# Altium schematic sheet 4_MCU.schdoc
size 309 x 223 mm; Symbol: Artery_A4; Device: Artery_A4; Company: Artery Technology; Drawed: SD; Version: 1.0; Page Size: A4; @Project Name: AT-START-F405; @Page Count: 4; @Update Date: 2023-08-23; @Create Date: 2023-05-06; @Schematic Name: AT-START-F405; @Page No: 2; @Page Name: MCU
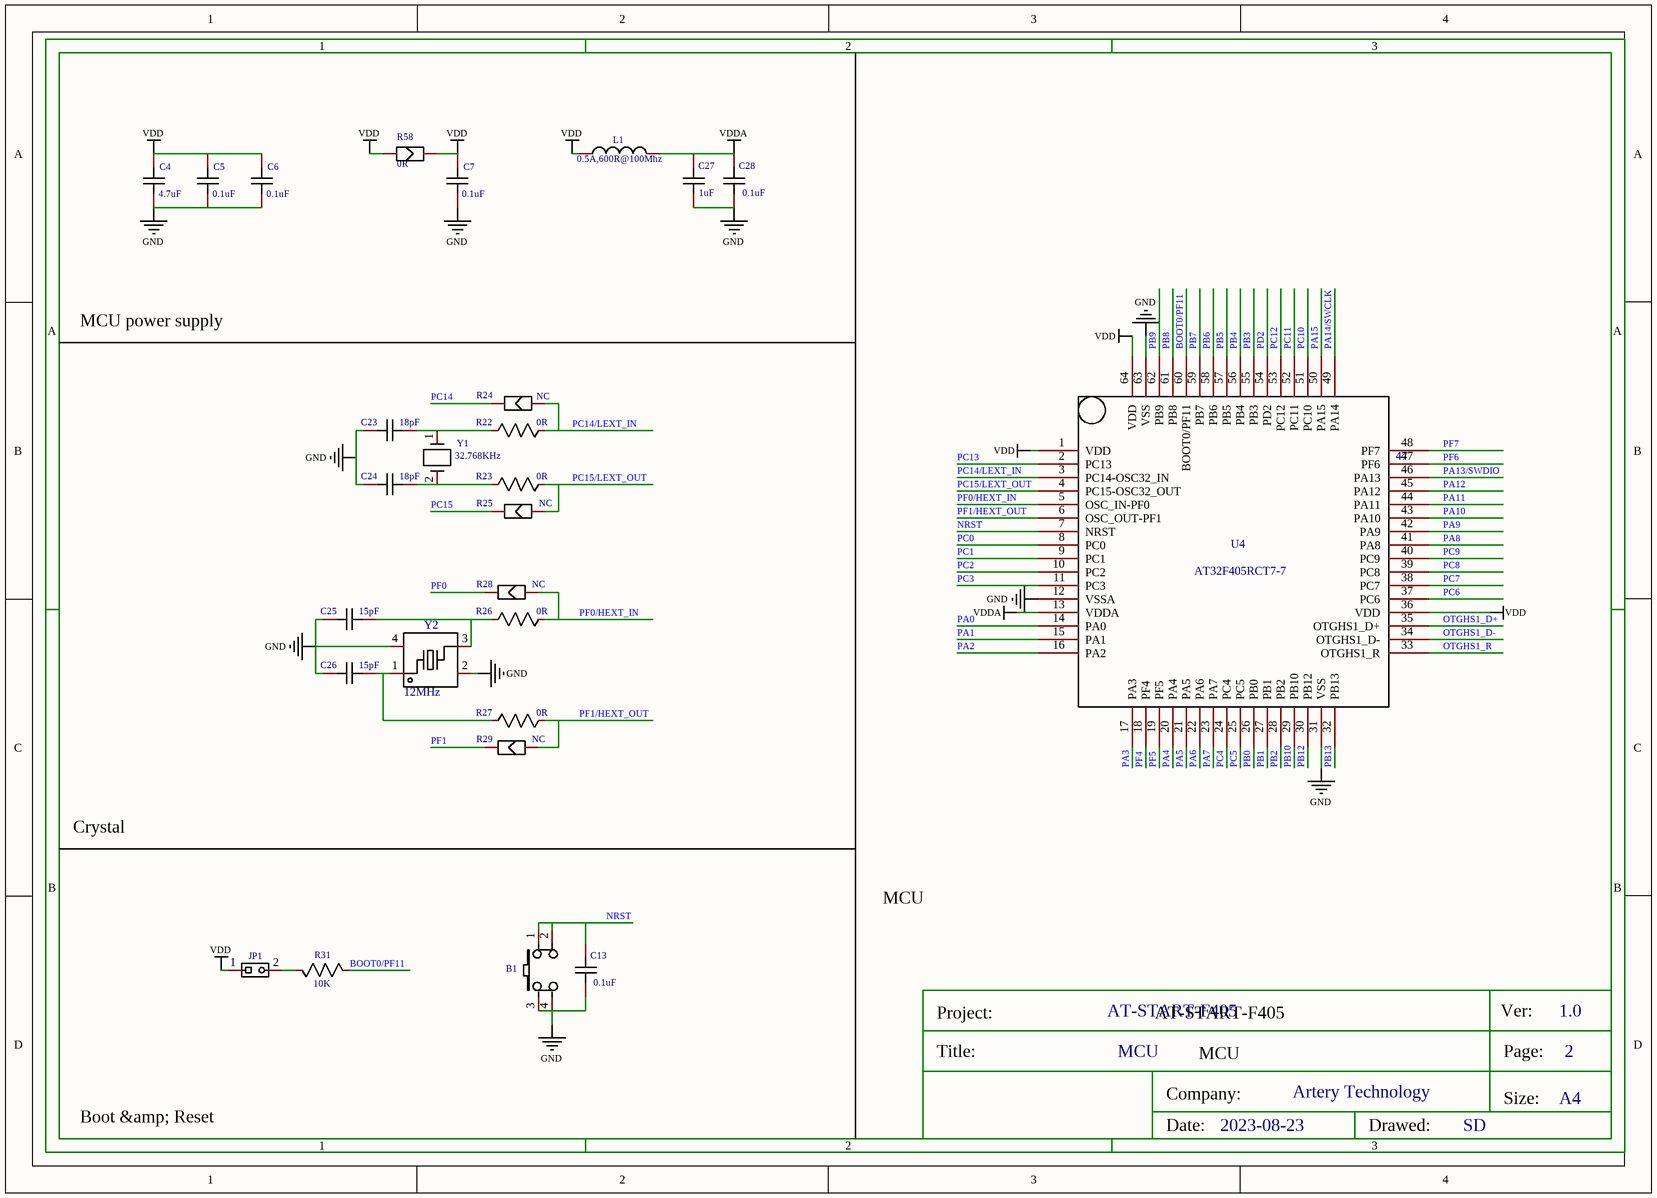
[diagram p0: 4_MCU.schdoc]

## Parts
B1  BUTTON_SMT,6.0x6.0x4.5mm  [BUTTON_SMT_6*6*5]  (value not drawn)
C4  4.7uF  [0603_C-M]
C5  0.1uF  [0603_C-M]
C6  0.1uF  [0603_C-M]
C7  0.1uF  [0603_C-M]
C13  0.1uF  [0603_C-M]
C23  18pF  [0603_C-M]
C24  18pF  [0603_C-M]
C25  15pF  [0603_C-M]
C26  15pF  [0603_C-M]
C27  1uF  [0603_C-M]
C28  0.1uF  [0603_C-M]
JP1  NC(Header 1x2)  [HEADER 1X2]  (value not drawn)
L1  0.5A,600R@100Mhz  [0603_L]
R22  0R  [0603_R-M]
R23  0R  [0603_R-M]
R24  NC  [SB-PAD]
R25  NC  [SB-PAD]
R26  0R  [0603_R-M]
R27  0R  [0603_R-M]
R28  NC  [SB-PAD]
R29  NC  [SB-PAD]
R31  10K  [0603_R-M]
R58  0R  [SB-PAD]
U4  NUMBER: 47  [LQFP-64_L10.0-W10.0-P0.50-LS12.0-TL]  (hidden comment: AT32F405RCT7-7)
Y1  32.768KHz  [XTAL_SOP - FC-12M]
Y2  value 12MHz  [CRYSTAL-SMD_4P-L3.2-W2.5-BL]  (hidden comment: CJ13-120001210B20)

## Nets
GND: B1.3 B1.4 C4.2 C5.2 C6.2 C7.2 C13.1 C23.1 C24.1 C25.1 C26.1 C27.1 C28.1 U4.12(VSSA) U4.31(VSS) U4.63(VSS) Y2.2(GND) Y2.4(GND)
VDD: C4.1 C5.1 C6.1 C7.1 JP1.1 L1.1 R58.1 R58.2 U4.1(VDD) U4.36(VDD) U4.64(VDD)
VDDA: C27.2 C28.2 L1.2 U4.13(VDDA)
BOOT0/PF11: R31.2 U4.60(BOOT0/PF11)
NRST: B1.1 B1.2 C13.2 U4.7(NRST)
OTGHS1_D+: U4.35(OTGHS1_D+)
OTGHS1_D-: U4.34(OTGHS1_D-)
OTGHS1_R: U4.33(OTGHS1_R)
PA0: U4.14(PA0)
PA1: U4.15(PA1)
PA2: U4.16(PA2)
PA3: U4.17(PA3)
PA4: U4.20(PA4)
PA5: U4.21(PA5)
PA6: U4.22(PA6)
PA7: U4.23(PA7)
PA8: U4.41(PA8)
PA9: U4.42(PA9)
PA10: U4.43(PA10)
PA11: U4.44(PA11)
PA12: U4.45(PA12)
PA13/SWDIO: U4.46(PA13)
PA14/SWCLK: U4.49(PA14)
PA15: U4.50(PA15)
PB0: U4.26(PB0)
PB1: U4.27(PB1)
PB2: U4.28(PB2)
PB3: U4.55(PB3)
PB4: U4.56(PB4)
PB5: U4.57(PB5)
PB6: U4.58(PB6)
PB7: U4.59(PB7)
PB8: U4.61(PB8)
PB9: U4.62(PB9)
PB10: U4.29(PB10)
PB12: U4.30(PB12)
PB13: U4.32(PB13)
PC0: U4.8(PC0)
PC1: U4.9(PC1)
PC2: U4.10(PC2)
PC3: U4.11(PC3)
PC4: U4.24(PC4)
PC5: U4.25(PC5)
PC6: U4.37(PC6)
PC7: U4.38(PC7)
PC8: U4.39(PC8)
PC9: U4.40(PC9)
PC10: U4.51(PC10)
PC11: U4.52(PC11)
PC12: U4.53(PC12)
PC13: U4.2(PC13)
PC14: R24.2
PC14/LEXT_IN: R22.1 R24.1 U4.3(PC14-OSC32_IN)
PC15: R25.2
PC15/LEXT_OUT: R23.1 R25.1 U4.4(PC15-OSC32_OUT)
PD2: U4.54(PD2)
PF0: R28.2
PF0/HEXT_IN: R26.1 R28.1 U4.5(OSC_IN-PF0)
PF1: R29.2
PF1/HEXT_OUT: R27.1 R29.1 U4.6(OSC_OUT-PF1)
PF4: U4.18(PF4)
PF5: U4.19(PF5)
PF6: U4.47(PF6)
PF7: U4.48(PF7)
NetC23_2: C23.2 R22.2 Y1.1
NetC24_2: C24.2 R23.2 Y1.2
NetC25_2: C25.2 R26.2 Y2.3
NetC26_2: C26.2 R27.2 Y2.1
NetJP1_2: JP1.2 R31.1

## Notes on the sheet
- MCU power supply
- Crystal
- MCU
- AT-START-F405
- Boot &amp; Reset

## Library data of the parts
B1 = BUTTON_SMT,6.0x6.0x4.5mm: Convert to PCB: yes
C4 = 4.7uF: Convert to PCB: yes
C5-C7 C13 C28 = 0.1uF: Convert to PCB: yes
C23 C24 = 10pF: Convert to PCB: yes
C25 C26 = 22pF: Convert to PCB: yes
C27 = 1uF: Convert to PCB: yes
JP1 = NC(Header 1x2): Convert to PCB: yes
L1 = 0.5A,600R@100Mhz: Convert to PCB: yes
R22 R23 R26 R27 = 0R: Convert to PCB: yes
R24 R25 R28 R29 R58 = NC: Convert to PCB: yes
R31 = 10K: Convert to PCB: yes
U4 = AT32F405Rx
Y1 = 32.768KHz: Convert to PCB: yes
Y2 = CJ13-120001210B20: 频率:12MHz;负载电容:12pF;; Manufacturer: CJ(江苏长电/长晶); Add into BOM: yes; Load Capacitance: 12pF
